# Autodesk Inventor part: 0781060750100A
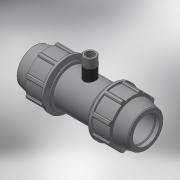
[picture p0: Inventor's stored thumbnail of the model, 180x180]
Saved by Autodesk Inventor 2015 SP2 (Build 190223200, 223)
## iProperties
Created: 2017-02
Part Number: 0781060750100A
Material: Generic
Description: PLASSON COUPLER WITH RISER 75-1"
Document SubType Name: Modeling
Designer: KIM
Mass: 1772.99 g
Surface Area: 2354.31 cm^2
Volume: 1772.99 cm^3
Density: 1 g/cm^3
Appearance: Default
Author: KIM
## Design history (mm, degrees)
derived "87810.ipt"
feature "Solid1::87810.ipt"
feature "Solid2::87810.ipt"
tag "TaggingFeature1"
body "Solid1"
other parameters: "d2" = 75, "d4" = 13.04167, "d5" = 37.56, "d7" = 134, "d11" = 5.21667, "d13" = 120 deg, "d14" = 97.5, "d15" = 12 deg, "d16" = 116.58, "d18" = 3.75, "d19" = 35 deg, "d20" = 17.5 deg, "d21" = 124.62, "d23" = 0, "d25" = 360 deg, "d27" = 2.68, "d33" = 1.5, "d42" = 56.34, "d43" = 4.02, "d46" = 2.25, "d68" = 5.21667, "d72" = 105, "d73" = 33.249, "d76" = 23.2743, "d77" = 24, "d80" = 0.99747, "d91" = 100.5, "d93" = 132, "d95" = 67.5, "d99" = 313, "d101" = 0, "d103" = 0, "d105" = 0, "d106" = 33.91398, "d107" = 6.26, "d108" = 0, "d_" = 75, "E_" = 134, "A_" = 105, "l_" = 132, "H_" = 313, "R_" = 33.249
